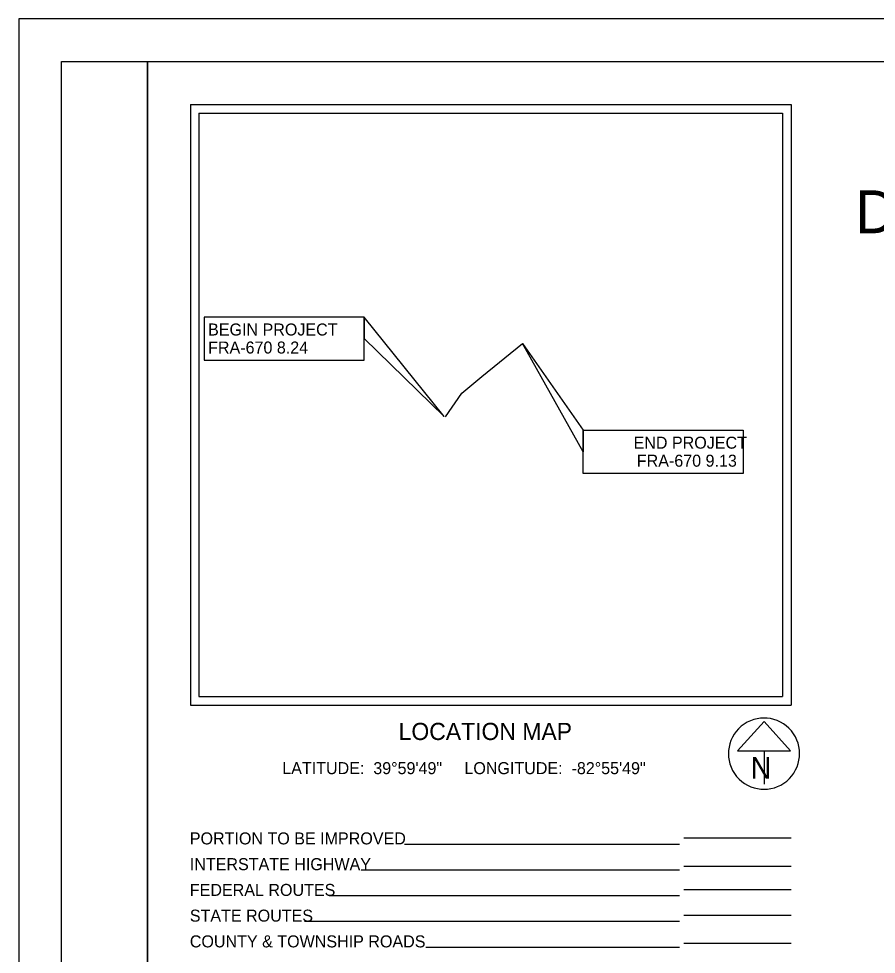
# Model space of a CAD drawing. Extents: x 0 to 34, y 0 to 22.
# Drawn here: x 0 to 9.99, y 11.1 to 22 of the extents above; entities that cross this region are included whole.
import ezdxf

# ---------------------------------------------------------------- set-up
doc = ezdxf.new("R2010")
doc.units = 0
for name, color, linetype in [('SH_Border', 7, 'Continuous'), ('SH_Cut_Line', 7, 'Continuous'), ('SH_Data', 7, 'Continuous'), ('SH_Text', 7, 'Continuous')]:
    doc.layers.add(name, color=color, linetype=linetype)

msp = doc.modelspace()

# ---------------------------------------------------------------- linework, layer by layer
at = {"layer": 'SH_Border'}
for points in [[(0.5, 21.5), (1.5, 21.5), (1.5, 0.5), (0.5, 0.5)], [(1.5, 21.5), (33.5, 21.5), (33.5, 0.5), (1.5, 0.5)]]:
    msp.add_lwpolyline(points, close=True, dxfattribs=at)
at = {"layer": 'SH_Cut_Line'}
msp.add_lwpolyline([(0, 0), (34, 0), (34, 22), (0, 22)], close=True, dxfattribs=at)
at = {"layer": 'SH_Data'}
for p, q in [((2, 21), (9, 21)), ((2, 21), (2, 14)), ((9, 21), (9, 14)), ((2.1, 20.9), (2.1, 14.1)), ((2.1, 20.9), (8.9, 20.9)), ((8.9, 20.9), (8.9, 14.1)), ((2.1, 14.1), (8.9, 14.1)), ((2.1, 14.1), (2.1, 14.1)), ((2, 14), (9, 14)), ((8.685, 13.809), (8.377, 13.468)), ((8.992, 13.468), (8.685, 13.809)), ((8.377, 13.468), (8.992, 13.468)), ((8.685, 13.468), (8.685, 13.081)), ((8.685, 13.435), (8.685, 13.435)), ((8.685, 13.435), (8.685, 13.435)), ((7.75, 12.455), (9, 12.455)), ((7.7, 12.377), (4.494, 12.377)), ((9, 12.121), (7.75, 12.121)), ((7.7, 12.077), (3.99, 12.077)), ((7.7, 11.777), (3.619, 11.777)), ((9, 11.849), (7.75, 11.849)), ((7.7, 11.477), (3.329, 11.477)), ((9, 11.549), (7.75, 11.549)), ((7.7, 11.177), (4.745, 11.177)), ((9, 11.222), (7.75, 11.222))]:
    msp.add_line(p, q, dxfattribs=at)
msp.add_lwpolyline([(4.975, 17.361), (5.165, 17.635), (5.395, 17.831), (5.869, 18.214)], dxfattribs=at)
msp.add_arc((8.685, 13.435), 0.415, 129.7798, 129.7633, dxfattribs=at)
at = {"layer": 'SH_Text'}
for points in [[(4.024, 18.02), (4.024, 18.523), (2.162, 18.523), (2.162, 18.02)], [(4.024, 18.272), (4.956, 17.364), (4.024, 18.523)], [(6.579, 16.952), (5.869, 18.214), (6.579, 17.204)], [(6.579, 16.701), (6.579, 17.204), (8.442, 17.204), (8.442, 16.701)]]:
    msp.add_lwpolyline(points, close=True, dxfattribs=at)

# ---------------------------------------------------------------- texts
at = {"layer": 'SH_Data'}
msp.add_text('N', height=0.25, dxfattribs=at).set_placement((8.529, 13.144))
at = {"layer": 'SH_Text'}
for s, height, p in [('DEPARTMENT OF TRANSPORTATION', 0.5, (9.747, 19.5)), ('BEGIN PROJECT', 0.14, (2.207, 18.308)), ('FRA-670 8.24', 0.14, (2.207, 18.098)), ('END PROJECT', 0.14, (7.165, 16.989)), ('FRA-670 9.13', 0.14, (7.203, 16.779)), ('LOCATION MAP', 0.2, (4.427, 13.594)), ('LATITUDE:  39°59\'49"     LONGITUDE:  -82°55\'49"', 0.14, (3.071, 13.196)), ('PORTION TO BE IMPROVED', 0.14, (1.994, 12.377)), ('INTERSTATE HIGHWAY', 0.14, (1.994, 12.077)), ('FEDERAL ROUTES', 0.14, (1.994, 11.777)), ('STATE ROUTES', 0.14, (1.994, 11.477)), ('COUNTY & TOWNSHIP ROADS', 0.14, (1.994, 11.177))]:
    msp.add_text(s, height=height, dxfattribs=at).set_placement(p)

doc.saveas('drawing.dxf')
